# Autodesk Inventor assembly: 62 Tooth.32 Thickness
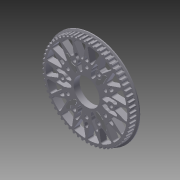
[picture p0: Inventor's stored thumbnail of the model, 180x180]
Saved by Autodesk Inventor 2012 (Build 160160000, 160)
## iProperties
Created: 2012-01
Part Number: 62 Tooth.32 Thickness
Document SubType Name: Assembly
Designer: Alex
Author: Alex
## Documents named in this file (5)
- C:\Users\Owner\Documents\Robotics\Mechanical Design\Parts\pulley\HTD\9mm\Double Flange\62 Tooth\62 Tooth.32 Thickness.iam
- C:\Users\Owner\Documents\Robotics\Mechanical Design\Parts\pulley\HTD\9mm\Double Flange\62 Tooth\HTD 5mm 62 Tooth rev001 step 2.ipt
- C:\Users\Owner\Documents\Robotics\Mechanical Design\Parts\pulley\HTD\9mm\Double Flange\62 Tooth\HTD 5mm 62 Tooth Flange_rev001.ipt
- C:\Users\Owner\Documents\Robotics\Mechanical Design\Parts\pulley\HTD\9mm\Double Flange\62 Tooth\Alignment Pin 1.ipt
- C:\Users\Owner\Documents\Robotics\Mechanical Design\Parts\pulley\HTD\9mm\Double Flange\62 Tooth\Alignment Pin 2.ipt
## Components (6 placed, 4 different names)
1. HTD 5mm 62 Tooth rev001 step 2:1 — Mate:1, Mate:2, Flush:1, Flush:2, Flush:3, Flush:4, Flush:5, Mate:3, Mate:4, Mate:5, Mate:6, Mate:7, Mate:8, Mate:9, Mate:10
2. HTD 5mm 62 Tooth Flange_rev001:1 — Mate:1, Mate:2
3. Alignment Pin 1:1 — Flush:5, Mate:7, Mate:8
4. Alignment Pin 2:1 — Flush:2, Mate:3, Mate:4
5. Alignment Pin 1:2 — Flush:4, Mate:9, Mate:10
6. Alignment Pin 2:2 — Flush:3, Mate:5, Mate:6
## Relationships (15: Mate 10, Flush 5)
- Mate:1: HTD 5mm 62 Tooth rev001 step 2:1 ↔ HTD 5mm 62 Tooth Flange_rev001:1
- Mate:2: HTD 5mm 62 Tooth rev001 step 2:1 ↔ HTD 5mm 62 Tooth Flange_rev001:1
- Flush:1: HTD 5mm 62 Tooth rev001 step 2:1
- Flush:2: HTD 5mm 62 Tooth rev001 step 2:1 ↔ Alignment Pin 2:1
- Flush:3: HTD 5mm 62 Tooth rev001 step 2:1 ↔ Alignment Pin 2:2
- Flush:4: HTD 5mm 62 Tooth rev001 step 2:1 ↔ Alignment Pin 1:2
- Flush:5: HTD 5mm 62 Tooth rev001 step 2:1 ↔ Alignment Pin 1:1
- Mate:3: HTD 5mm 62 Tooth rev001 step 2:1 ↔ Alignment Pin 2:1
- Mate:4: HTD 5mm 62 Tooth rev001 step 2:1 ↔ Alignment Pin 2:1
- Mate:5: HTD 5mm 62 Tooth rev001 step 2:1 ↔ Alignment Pin 2:2
- Mate:6: HTD 5mm 62 Tooth rev001 step 2:1 ↔ Alignment Pin 2:2
- Mate:7: HTD 5mm 62 Tooth rev001 step 2:1 ↔ Alignment Pin 1:1
- Mate:8: HTD 5mm 62 Tooth rev001 step 2:1 ↔ Alignment Pin 1:1
- Mate:9: HTD 5mm 62 Tooth rev001 step 2:1 ↔ Alignment Pin 1:2
- Mate:10: HTD 5mm 62 Tooth rev001 step 2:1 ↔ Alignment Pin 1:2
